(* Logix 5000 project; controller EFR_Cntrl vendor 1 type 14 code 74 rev 20.12; software revision 20.01 *)

TASK MainTask (continuous, watchdog 500 ms) : MainProgram

MODULES
   Local : vendor 1 type 14 code 74 (1768Ctrl5Slot 0, Compact 0, rev 20.12)
      ENET : 1768-ENBT (Ethernet 10.10.20.11, 1768 1, rev 3.1)
         EFRCGM_19A796 : ETHERNET-MODULE (Ethernet 10.10.20.16, rev 1.1, Output RPI 10 ms)   // Graco CGM Map 19A796
END_MODULES

TYPE ActiveErrorNumber :
STRUCT
   ActiveErrorToAcknowledgeCntrl : SINT;
   ActiveErrorToAcknowledgeStatus : SINT;
END_STRUCT
END_TYPE

TYPE ActiveSequenceStep :
STRUCT
   ActiveSequenceDesiredStepCntrl : SINT;
   ActiveSequenceDesiredStepAmountCntrl : DINT;
   ActiveSequenceDesiredStepStepTypeCntrl : SINT;
   ActiveSequenceDesiredStepFlowRateCntrl : INT;
   ActiveSequenceDesireStepCalibrationCntrl : INT;
   ActiveSequenceActualStepStatus : SINT;
   ActiveSequenceActualStepAmountStatus : DINT;
   ActiveSequenceActualStepTypeStatus : SINT;
   ActiveSequenceActualFlowRateStatus : INT;
   ActiveSequenceActualCalibrationStatus : INT;
END_STRUCT
END_TYPE

TYPE DataExchange :
STRUCT
   DataExchangedDesiredElementCntrl : SINT;
   DataExchangeElementDesiredValueCntrl : INT;
   DataExchangedActualElementStatus : SINT;
   DataExchangedActualElementValueStatus : INT;
END_STRUCT
END_TYPE

TYPE EFRPumpInformation :
STRUCT
   RedPumpOutletPressure : INT;
   BluePumpOutletPressure : INT;
   RedPumpInletPressure : INT;
   BluePumpInletPressure : INT;
   PumpFlowRate : INT;
END_STRUCT
END_TYPE

TYPE EFRSequenceInformation :
STRUCT
   TotalSequenceAmountRequested : DINT;
   TotalSequenceAmountDispensed : DINT;
END_STRUCT
END_TYPE

TYPE EFRSystemInformation :
STRUCT
   DesiredActiveSequence : SINT;
   CurrentActiveSequenceSelected : SINT;
   CurrentActiveStepOfSequenceSelected : SINT;
   TimeRemindingtoCompleteCurrentStep : INT;
END_STRUCT
END_TYPE

TYPE HeartbeatLogic :
STRUCT
   HeartbeatFailure : BOOL;
   EFRIsDisconnected : BOOL;
   Heartbeat_HighMonitor : COUNTER;
   Heartbeat_LowMonitor : COUNTER;
   Heartbeat_MonitorTimer : TIMER;
   Heartbeat_StopMonitorTimer : BOOL;
END_STRUCT
END_TYPE

TYPE OperatorModeOverrideFlowRate :
STRUCT
   OperatorModeDesiredFlowRate : INT;
   OperatorModeActiveFlowRate : INT;
END_STRUCT
END_TYPE

TYPE SystemBooleansCntrl :
STRUCT
   SystemEnabledRequest : BOOL;
   SystemShutdownRequest : BOOL;
   StartCurrentSequenceStep_Trigger : BOOL;
   PauseSequence : BOOL;
   StopSequence : BOOL;
   PrimingRequest : BOOL;
   PurgeRequest : BOOL;
   ParkingRequest : BOOL;
   DepressurizingRequest : BOOL;
   ADM_Lockout_Request : BOOL;
   Increment_StepTime_Request : BOOL;
   PLC_Monitor_Only_Request : BOOL;
   PLC_toEFR_Heartbeat_Enable_Request : BOOL;
   PLC_HeartBeat_to_EFR : BOOL;
   DMV_MotorOn_Request : BOOL;
   DMV_AirInjectionValveOn_Request : BOOL;
   RecirculationRequest : BOOL;
END_STRUCT
END_TYPE

TYPE SystemBooleansStatus :
STRUCT
   HeartbeatToPLC : BOOL;
   SystemOn : BOOL;
   SystemReady : BOOL;
   AlarmsPresent : BOOL;
   DeviationsPresent : BOOL;
   AdvisoriesPresent : BOOL;
   CurrentSequenceIsPlaying : BOOL;
   CurrentSequenceIsPaused : BOOL;
   CurrentSequenceIsStopped : BOOL;
   DispenseValveOpen : BOOL;
   SystemIsPriming : BOOL;
   SystemIsPurging : BOOL;
   SystemIsParking : BOOL;
   SystemIsDepressurizing : BOOL;
   GelTimeShotIsDispensing : BOOL;
   EFRIsDispensing : BOOL;
   ADM_Lockout_is_Active : BOOL;
   Incrementing_StepTime_is_Active : BOOL;
   PLC_Monitor_Only_is_Active : BOOL;
   PLC_toEFR_HeatbeatIs_Enabled_andRequired : BOOL;
   DMV_MotorRunning : BOOL;
   DMV_EFRDispenseWaitCompletedForDispense : BOOL;   // EFR Wait Completed for Dispensing is a bollean that is used only when EFR Dispense Wait is Enabled. This boolean will remind low while the EFR is waiting for the Voltex to get up to speed, after a dispense is triggered. Once up to speed, the variable will be set high and the machine will start dispensing
   DMV_MotorAtTargetSpeed : BOOL;
   DMV_AirInjectionValveOpen : BOOL;
   SystemIsRecirculating : BOOL;
END_STRUCT
END_TYPE

TYPE TankBooleans :
STRUCT
   ManualRefillRequest : BOOL;
   RefillActiveStatus : BOOL;
   LevelSensorBit1 : BOOL;   // Bit1 Bit2 Result 0 0 Error 1 0 Low 0 1 Mid 1 1 High
   LevelSensorBit2 : BOOL;   // Bit1 Bit2 Result 0 0 Error 1 0 Low 0 1 Mid 1 1 High
END_STRUCT
END_TYPE

TYPE TankStands :
STRUCT
   RedTank : TankBooleans;
   BlueTank : TankBooleans;
END_STRUCT
END_TYPE

VAR_GLOBAL   (* controller tags *)
   ActiveErrorAcknowledgement : ActiveErrorNumber;
   DataExchange : DataExchange;
   EFRPumpInformation : EFRPumpInformation; {access Read Only}
   EFRSystemInformation : EFRSystemInformation;
   Enable_PLC_HeartBeatOut : BOOL;
   HeartbeatLogic : HeartbeatLogic := (Heartbeat_HighMonitor.PRE := 2, Heartbeat_LowMonitor.PRE := 2, Heartbeat_MonitorTimer.PRE := 20000); {access Read Only}
   OperatorModeFlowRate : OperatorModeOverrideFlowRate;
   SequenceActiveStep : ActiveSequenceStep;
   SequenceDispenseInformation : EFRSequenceInformation; {access Read Only}
   SystemBooleansCntrl : SystemBooleansCntrl;
   SystemBooleansStatus : SystemBooleansStatus; {access Read Only}
   TankStands : TankStands; {access Read Only}
END_VAR

PROGRAM MainProgram   (* main routine MainRoutine *)

ROUTINE MainRoutine   (* ladder *)
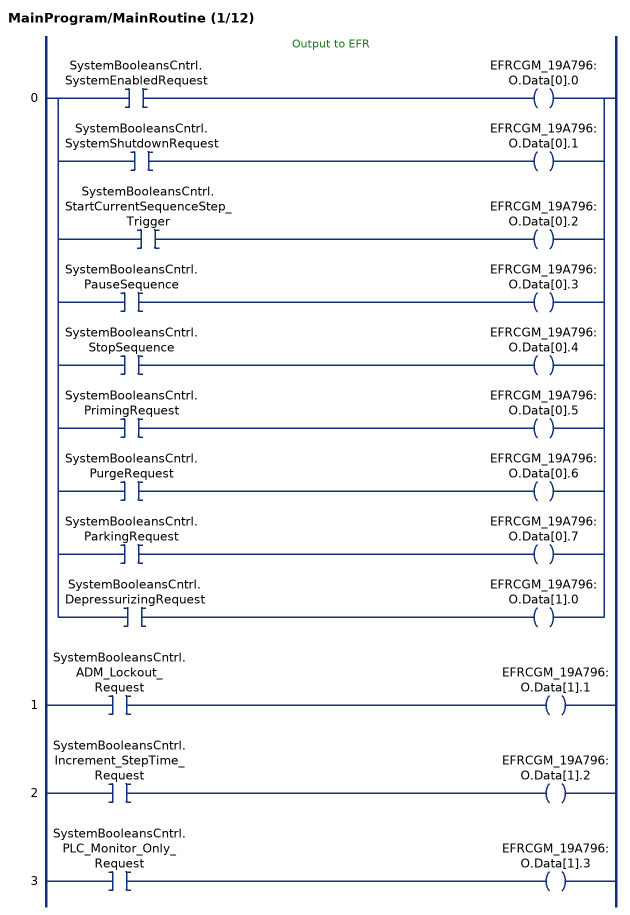
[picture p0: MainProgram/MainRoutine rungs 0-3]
   // Output to EFR
   0: [XIC(SystemBooleansCntrl.SystemEnabledRequest) OTE(EFRCGM_19A796:O.Data[0].0) ,XIC(SystemBooleansCntrl.SystemShutdownRequest) OTE(EFRCGM_19A796:O.Data[0].1) ,XIC(SystemBooleansCntrl.StartCurrentSequenceStep_Trigger) OTE(EFRCGM_19A796:O.Data[0].2) ,XIC(SystemBooleansCntrl.PauseSequence) OTE(EFRCGM_19A796:O.Data[0].3) ,XIC(SystemBooleansCntrl.StopSequence) OTE(EFRCGM_19A796:O.Data[0].4) ,XIC(SystemBooleansCntrl.PrimingRequest) OTE(EFRCGM_19A796:O.Data[0].5) ,XIC(SystemBooleansCntrl.PurgeRequest) OTE(EFRCGM_19A796:O.Data[0].6) ,XIC(SystemBooleansCntrl.ParkingRequest) OTE(EFRCGM_19A796:O.Data[0].7) ,XIC(SystemBooleansCntrl.DepressurizingRequest) OTE(EFRCGM_19A796:O.Data[1].0) ];
   1: XIC(SystemBooleansCntrl.ADM_Lockout_Request)OTE(EFRCGM_19A796:O.Data[1].1);
   2: XIC(SystemBooleansCntrl.Increment_StepTime_Request)OTE(EFRCGM_19A796:O.Data[1].2);
   3: XIC(SystemBooleansCntrl.PLC_Monitor_Only_Request)OTE(EFRCGM_19A796:O.Data[1].3);
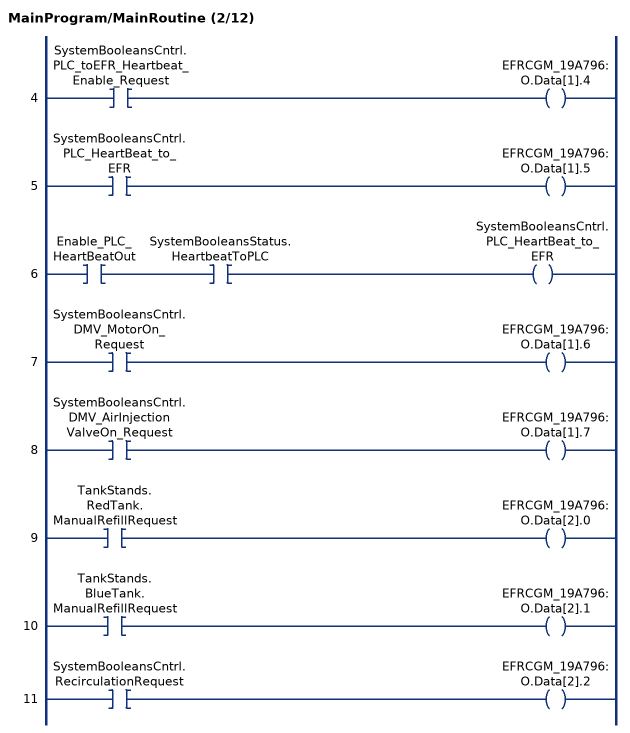
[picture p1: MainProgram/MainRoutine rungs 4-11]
   4: XIC(SystemBooleansCntrl.PLC_toEFR_Heartbeat_Enable_Request)OTE(EFRCGM_19A796:O.Data[1].4);
   5: XIC(SystemBooleansCntrl.PLC_HeartBeat_to_EFR)OTE(EFRCGM_19A796:O.Data[1].5);
   6: XIC(Enable_PLC_HeartBeatOut)XIC(SystemBooleansStatus.HeartbeatToPLC)OTE(SystemBooleansCntrl.PLC_HeartBeat_to_EFR);
   7: XIC(SystemBooleansCntrl.DMV_MotorOn_Request)OTE(EFRCGM_19A796:O.Data[1].6);
   8: XIC(SystemBooleansCntrl.DMV_AirInjectionValveOn_Request)OTE(EFRCGM_19A796:O.Data[1].7);
   9: XIC(TankStands.RedTank.ManualRefillRequest)OTE(EFRCGM_19A796:O.Data[2].0);
   10: XIC(TankStands.BlueTank.ManualRefillRequest)OTE(EFRCGM_19A796:O.Data[2].1);
   11: XIC(SystemBooleansCntrl.RecirculationRequest)OTE(EFRCGM_19A796:O.Data[2].2);
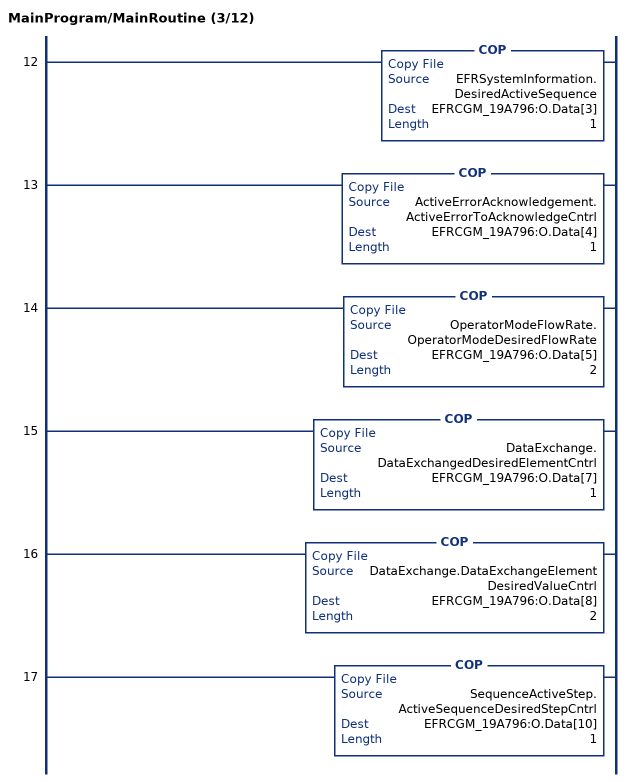
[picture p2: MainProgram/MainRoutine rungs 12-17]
   12: COP(EFRSystemInformation.DesiredActiveSequence,EFRCGM_19A796:O.Data[3],1);
   13: COP(ActiveErrorAcknowledgement.ActiveErrorToAcknowledgeCntrl,EFRCGM_19A796:O.Data[4],1);
   14: COP(OperatorModeFlowRate.OperatorModeDesiredFlowRate,EFRCGM_19A796:O.Data[5],2);
   15: COP(DataExchange.DataExchangedDesiredElementCntrl,EFRCGM_19A796:O.Data[7],1);
   16: COP(DataExchange.DataExchangeElementDesiredValueCntrl,EFRCGM_19A796:O.Data[8],2);
   17: COP(SequenceActiveStep.ActiveSequenceDesiredStepCntrl,EFRCGM_19A796:O.Data[10],1);
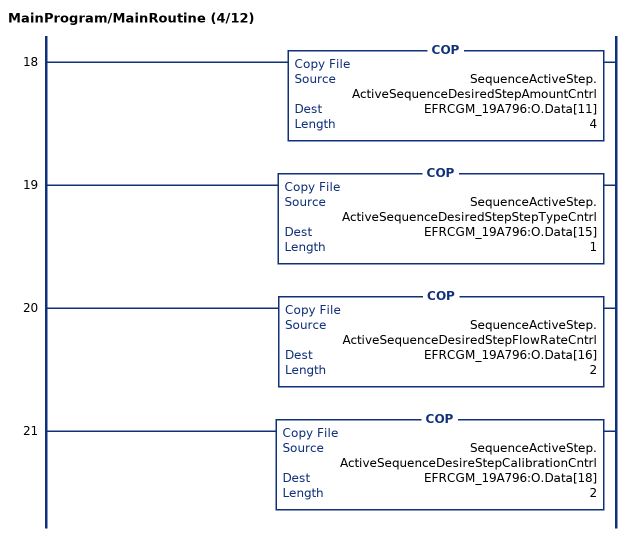
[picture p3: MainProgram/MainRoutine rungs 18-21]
   18: COP(SequenceActiveStep.ActiveSequenceDesiredStepAmountCntrl,EFRCGM_19A796:O.Data[11],4);
   19: COP(SequenceActiveStep.ActiveSequenceDesiredStepStepTypeCntrl,EFRCGM_19A796:O.Data[15],1);
   20: COP(SequenceActiveStep.ActiveSequenceDesiredStepFlowRateCntrl,EFRCGM_19A796:O.Data[16],2);
   21: COP(SequenceActiveStep.ActiveSequenceDesireStepCalibrationCntrl,EFRCGM_19A796:O.Data[18],2);
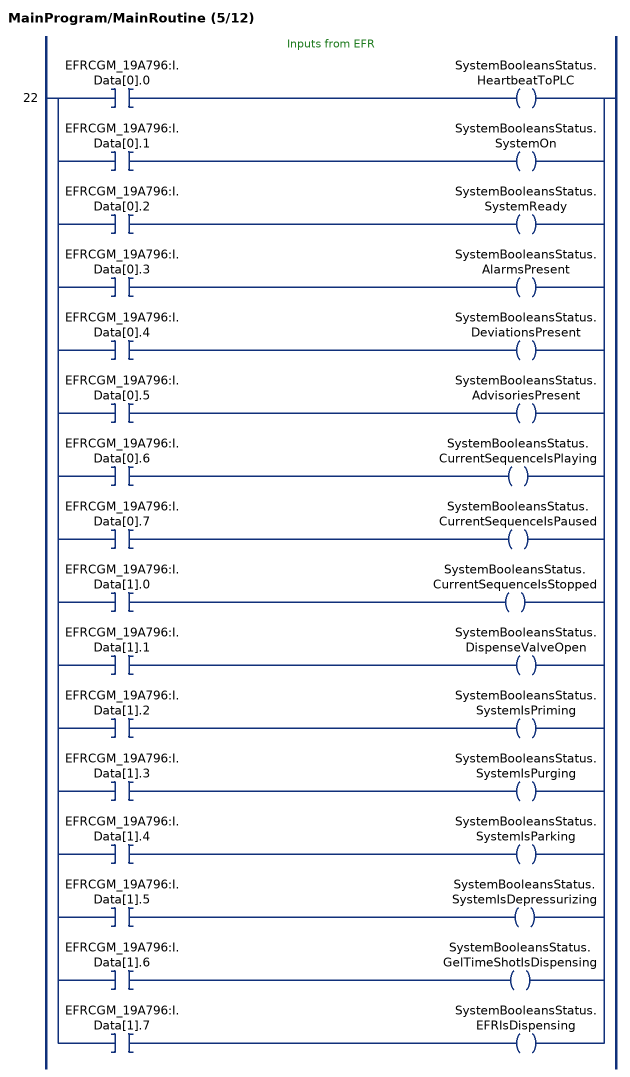
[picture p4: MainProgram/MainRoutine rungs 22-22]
   // Inputs from EFR
   22: [XIC(EFRCGM_19A796:I.Data[0].0) OTE(SystemBooleansStatus.HeartbeatToPLC) ,XIC(EFRCGM_19A796:I.Data[0].1) OTE(SystemBooleansStatus.SystemOn) ,XIC(EFRCGM_19A796:I.Data[0].2) OTE(SystemBooleansStatus.SystemReady) ,XIC(EFRCGM_19A796:I.Data[0].3) OTE(SystemBooleansStatus.AlarmsPresent) ,XIC(EFRCGM_19A796:I.Data[0].4) OTE(SystemBooleansStatus.DeviationsPresent) ,XIC(EFRCGM_19A796:I.Data[0].5) OTE(SystemBooleansStatus.AdvisoriesPresent) ,XIC(EFRCGM_19A796:I.Data[0].6) OTE(SystemBooleansStatus.CurrentSequenceIsPlaying) ,XIC(EFRCGM_19A796:I.Data[0].7) OTE(SystemBooleansStatus.CurrentSequenceIsPaused) ,XIC(EFRCGM_19A796:I.Data[1].0) OTE(SystemBooleansStatus.CurrentSequenceIsStopped) ,XIC(EFRCGM_19A796:I.Data[1].1) OTE(SystemBooleansStatus.DispenseValveOpen) ,XIC(EFRCGM_19A796:I.Data[1].2) OTE(SystemBooleansStatus.SystemIsPriming) ,XIC(EFRCGM_19A796:I.Data[1].3) OTE(SystemBooleansStatus.SystemIsPurging) ,XIC(EFRCGM_19A796:I.Data[1].4) OTE(SystemBooleansStatus.SystemIsParking) ,XIC(EFRCGM_19A796:I.Data[1].5) OTE(SystemBooleansStatus.SystemIsDepressurizing) ,XIC(EFRCGM_19A796:I.Data[1].6) OTE(SystemBooleansStatus.GelTimeShotIsDispensing) ,XIC(EFRCGM_19A796:I.Data[1].7) OTE(SystemBooleansStatus.EFRIsDispensing) ];
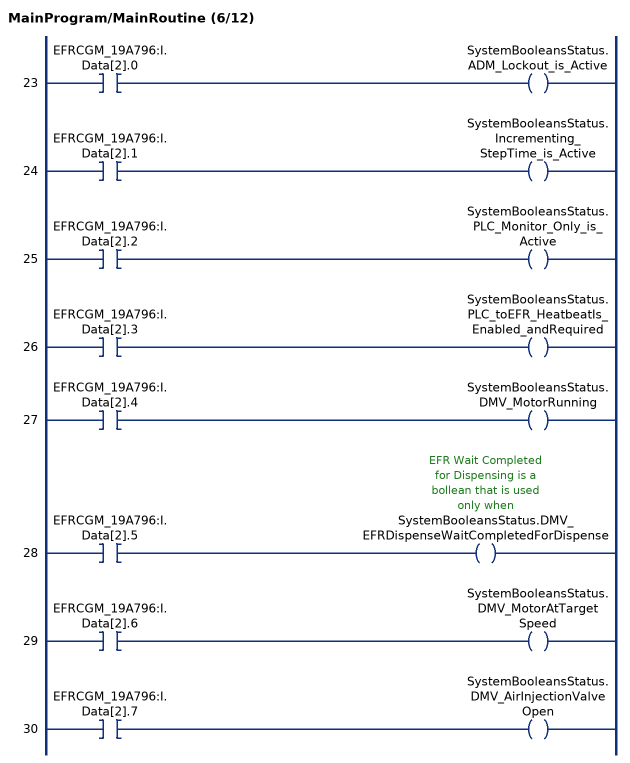
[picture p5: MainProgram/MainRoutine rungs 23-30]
   23: XIC(EFRCGM_19A796:I.Data[2].0)OTE(SystemBooleansStatus.ADM_Lockout_is_Active);
   24: XIC(EFRCGM_19A796:I.Data[2].1)OTE(SystemBooleansStatus.Incrementing_StepTime_is_Active);
   25: XIC(EFRCGM_19A796:I.Data[2].2)OTE(SystemBooleansStatus.PLC_Monitor_Only_is_Active);
   26: XIC(EFRCGM_19A796:I.Data[2].3)OTE(SystemBooleansStatus.PLC_toEFR_HeatbeatIs_Enabled_andRequired);
   27: XIC(EFRCGM_19A796:I.Data[2].4)OTE(SystemBooleansStatus.DMV_MotorRunning);
   28: XIC(EFRCGM_19A796:I.Data[2].5)OTE(SystemBooleansStatus.DMV_EFRDispenseWaitCompletedForDispense);
   29: XIC(EFRCGM_19A796:I.Data[2].6)OTE(SystemBooleansStatus.DMV_MotorAtTargetSpeed);
   30: XIC(EFRCGM_19A796:I.Data[2].7)OTE(SystemBooleansStatus.DMV_AirInjectionValveOpen);
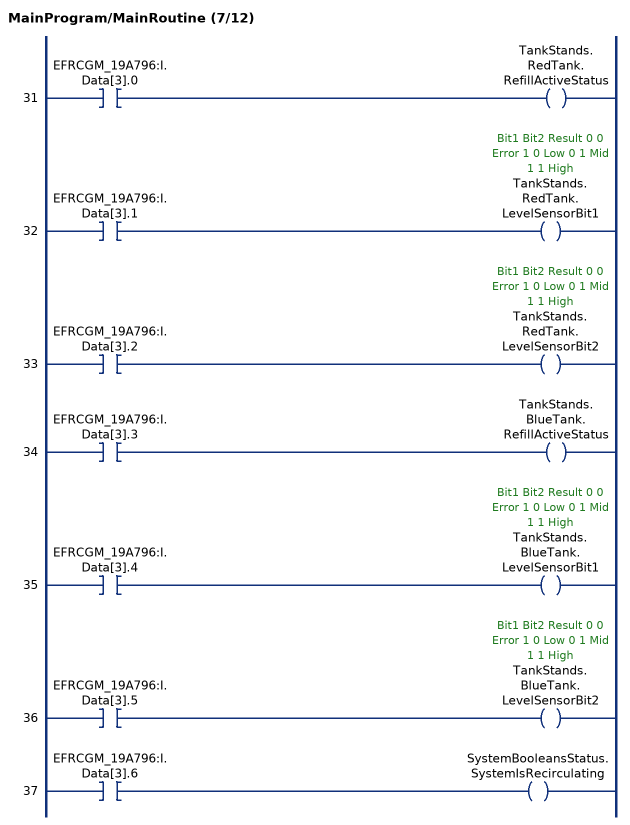
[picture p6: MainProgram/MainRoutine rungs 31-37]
   31: XIC(EFRCGM_19A796:I.Data[3].0)OTE(TankStands.RedTank.RefillActiveStatus);
   32: XIC(EFRCGM_19A796:I.Data[3].1)OTE(TankStands.RedTank.LevelSensorBit1);
   33: XIC(EFRCGM_19A796:I.Data[3].2)OTE(TankStands.RedTank.LevelSensorBit2);
   34: XIC(EFRCGM_19A796:I.Data[3].3)OTE(TankStands.BlueTank.RefillActiveStatus);
   35: XIC(EFRCGM_19A796:I.Data[3].4)OTE(TankStands.BlueTank.LevelSensorBit1);
   36: XIC(EFRCGM_19A796:I.Data[3].5)OTE(TankStands.BlueTank.LevelSensorBit2);
   37: XIC(EFRCGM_19A796:I.Data[3].6)OTE(SystemBooleansStatus.SystemIsRecirculating);
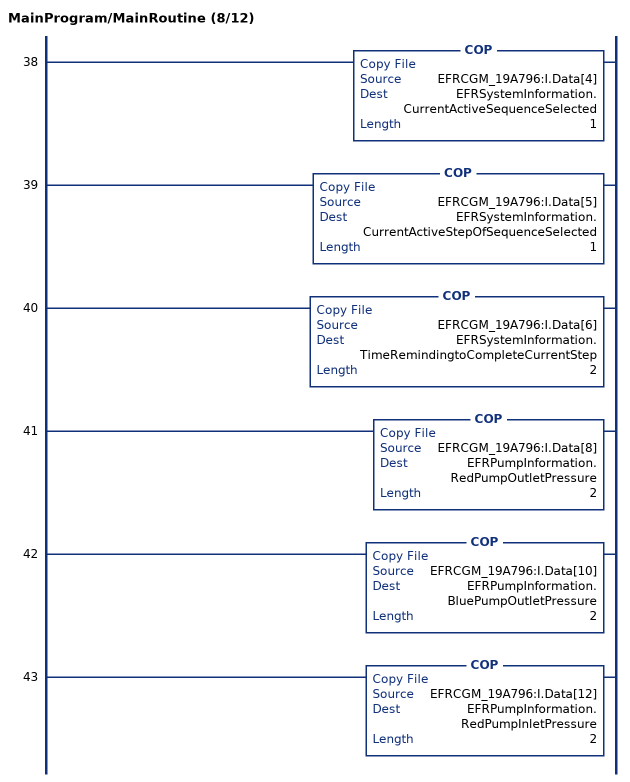
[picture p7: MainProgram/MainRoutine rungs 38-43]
   38: COP(EFRCGM_19A796:I.Data[4],EFRSystemInformation.CurrentActiveSequenceSelected,1);
   39: COP(EFRCGM_19A796:I.Data[5],EFRSystemInformation.CurrentActiveStepOfSequenceSelected,1);
   40: COP(EFRCGM_19A796:I.Data[6],EFRSystemInformation.TimeRemindingtoCompleteCurrentStep,2);
   41: COP(EFRCGM_19A796:I.Data[8],EFRPumpInformation.RedPumpOutletPressure,2);
   42: COP(EFRCGM_19A796:I.Data[10],EFRPumpInformation.BluePumpOutletPressure,2);
   43: COP(EFRCGM_19A796:I.Data[12],EFRPumpInformation.RedPumpInletPressure,2);
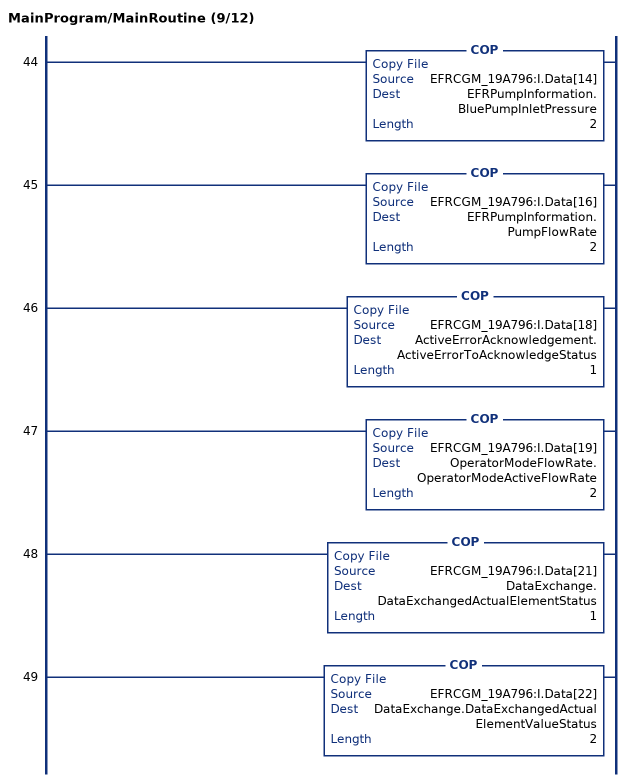
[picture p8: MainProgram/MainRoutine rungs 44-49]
   44: COP(EFRCGM_19A796:I.Data[14],EFRPumpInformation.BluePumpInletPressure,2);
   45: COP(EFRCGM_19A796:I.Data[16],EFRPumpInformation.PumpFlowRate,2);
   46: COP(EFRCGM_19A796:I.Data[18],ActiveErrorAcknowledgement.ActiveErrorToAcknowledgeStatus,1);
   47: COP(EFRCGM_19A796:I.Data[19],OperatorModeFlowRate.OperatorModeActiveFlowRate,2);
   48: COP(EFRCGM_19A796:I.Data[21],DataExchange.DataExchangedActualElementStatus,1);
   49: COP(EFRCGM_19A796:I.Data[22],DataExchange.DataExchangedActualElementValueStatus,2);
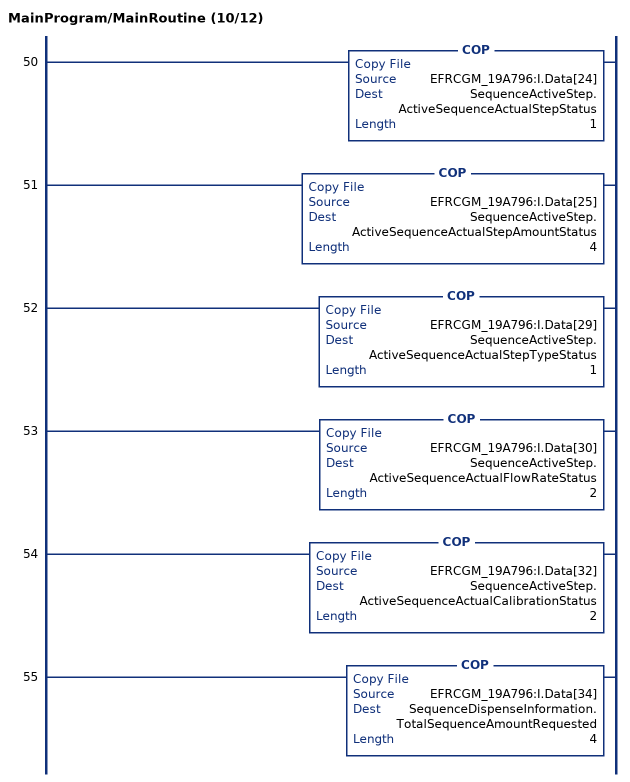
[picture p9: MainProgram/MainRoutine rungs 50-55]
   50: COP(EFRCGM_19A796:I.Data[24],SequenceActiveStep.ActiveSequenceActualStepStatus,1);
   51: COP(EFRCGM_19A796:I.Data[25],SequenceActiveStep.ActiveSequenceActualStepAmountStatus,4);
   52: COP(EFRCGM_19A796:I.Data[29],SequenceActiveStep.ActiveSequenceActualStepTypeStatus,1);
   53: COP(EFRCGM_19A796:I.Data[30],SequenceActiveStep.ActiveSequenceActualFlowRateStatus,2);
   54: COP(EFRCGM_19A796:I.Data[32],SequenceActiveStep.ActiveSequenceActualCalibrationStatus,2);
   55: COP(EFRCGM_19A796:I.Data[34],SequenceDispenseInformation.TotalSequenceAmountRequested,4);
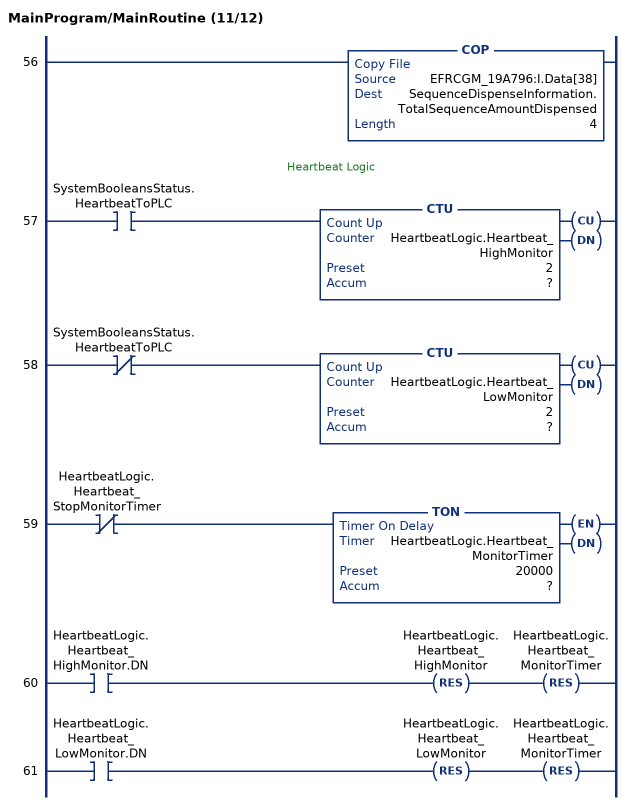
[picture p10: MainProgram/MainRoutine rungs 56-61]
   56: COP(EFRCGM_19A796:I.Data[38],SequenceDispenseInformation.TotalSequenceAmountDispensed,4);
   // Heartbeat Logic
   57: XIC(SystemBooleansStatus.HeartbeatToPLC)CTU(HeartbeatLogic.Heartbeat_HighMonitor,?,?);
   58: XIO(SystemBooleansStatus.HeartbeatToPLC)CTU(HeartbeatLogic.Heartbeat_LowMonitor,?,?);
   59: XIO(HeartbeatLogic.Heartbeat_StopMonitorTimer)TON(HeartbeatLogic.Heartbeat_MonitorTimer,?,?);
   60: XIC(HeartbeatLogic.Heartbeat_HighMonitor.DN)RES(HeartbeatLogic.Heartbeat_HighMonitor)RES(HeartbeatLogic.Heartbeat_MonitorTimer);
   61: XIC(HeartbeatLogic.Heartbeat_LowMonitor.DN)RES(HeartbeatLogic.Heartbeat_LowMonitor)RES(HeartbeatLogic.Heartbeat_MonitorTimer);
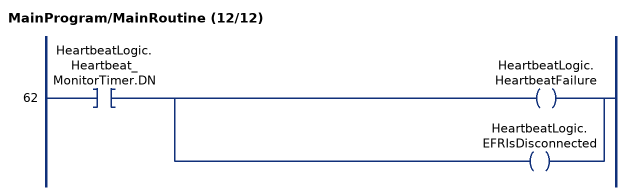
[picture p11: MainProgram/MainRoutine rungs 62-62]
   62: XIC(HeartbeatLogic.Heartbeat_MonitorTimer.DN)[OTE(HeartbeatLogic.HeartbeatFailure) ,OTE(HeartbeatLogic.EFRIsDisconnected) ];
END_ROUTINE
END_PROGRAM
